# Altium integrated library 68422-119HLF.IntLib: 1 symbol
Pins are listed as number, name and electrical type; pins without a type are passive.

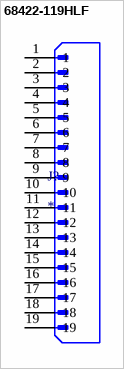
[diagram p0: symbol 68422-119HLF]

## 68422-119HLF
designator J?
BergStikÂ® 2.54mm, Board To Board Connector, Unshrouded Header, Through Hole, Single Row, 19 Positions, 2.54mm Pitch, Vertical, 8.08mm (0.318in) Mating, 5.41mm (0.213in) Tail.; MF: Amphenol; MP: 68422-119HLF
footprint AMPHENOL_68422-119HLF
pins: 1, 2, 3, 4, 5, 6, 7, 8, 9, 10, 11, 12, 13, 14, 15, 16, 17, 18, 19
